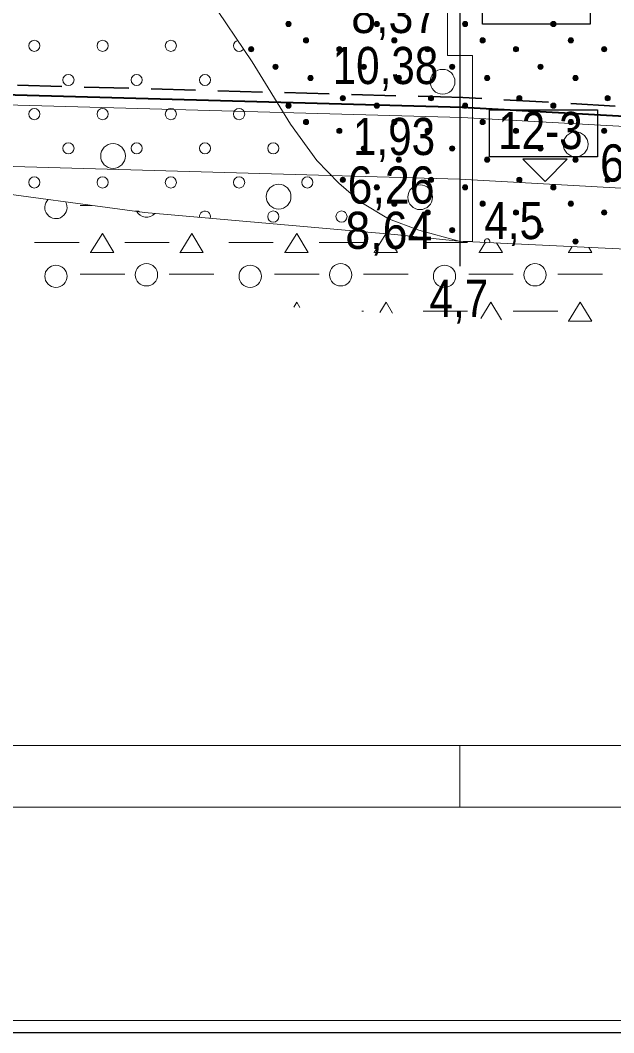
# Model space of a CAD drawing. Extents: x 640104 to 640970, y 6442278 to 6442689.
# Drawn here: x 640378.9 to 640426.8, y 6442282.5 to 6442364.3 of the extents above; entities that cross this region are included whole.
import ezdxf
from ezdxf.enums import TextEntityAlignment as Align

# ---------------------------------------------------------------- set-up
doc = ezdxf.new("R2010")
doc.units = 0
doc.header["$LTSCALE"] = 1.2
doc.linetypes.add('MEDIUM_DASHED', pattern=[4.5, 3, -1.5])
for name, color, linetype, lineweight in [('30', 7, 'Continuous', 13), ('31', 7, 'Continuous', 13), ('32', 7, 'Continuous', 25), ('33', 7, 'Continuous', 13), ('34', 7, 'Continuous', 25), ('35', 7, 'Continuous', 35), ('42', 7, 'Continuous', 13), ('44', 7, 'Continuous', 13), ('46', 7, 'Continuous', 13), ('47', 7, 'Continuous', 13), ('50', 7, 'Continuous', 13)]:
    doc.layers.add(name, color=color, linetype=linetype, lineweight=lineweight)

msp = doc.modelspace()

# ---------------------------------------------------------------- hatches: boundary and pattern name
at = {"layer": '44'}
for points in [[(640400.776, 6442364.001, 1), (640400.356, 6442364.001, 1)], [(640407.909, 6442364.001, 1), (640407.489, 6442364.001, 1)], [(640415.042, 6442364.001, 1), (640414.622, 6442364.001, 1)], [(640422.175, 6442364.001, 1), (640421.755, 6442364.001, 1)], [(640402.195, 6442362.679, 1), (640401.775, 6442362.679, 1)], [(640409.328, 6442362.679, 1), (640408.908, 6442362.679, 1)], [(640416.461, 6442362.679, 1), (640416.041, 6442362.679, 1)], [(640423.594, 6442362.679, 1), (640423.174, 6442362.679, 1)], [(640397.754, 6442361.963, 1), (640397.334, 6442361.963, 1)], [(640404.887, 6442361.963, 1), (640404.467, 6442361.963, 1)], [(640412.02, 6442361.963, 1), (640411.6, 6442361.963, 1)], [(640419.153, 6442361.963, 1), (640418.733, 6442361.963, 1)], [(640426.286, 6442361.963, 1), (640425.866, 6442361.963, 1)], [(640399.732, 6442360.544, 1), (640399.312, 6442360.544, 1)], [(640406.865, 6442360.544, 1), (640406.445, 6442360.544, 1)], [(640413.998, 6442360.544, 1), (640413.578, 6442360.544, 1)], [(640421.131, 6442360.544, 1), (640420.711, 6442360.544, 1)], [(640402.559, 6442359.636, 1), (640402.139, 6442359.636, 1)], [(640409.692, 6442359.636, 1), (640409.272, 6442359.636, 1)], [(640416.825, 6442359.636, 1), (640416.405, 6442359.636, 1)], [(640423.958, 6442359.636, 1), (640423.538, 6442359.636, 1)], [(640405.161, 6442358.01, 1), (640404.741, 6442358.01, 1)], [(640412.294, 6442358.01, 1), (640411.874, 6442358.01, 1)], [(640419.427, 6442358.01, 1), (640419.007, 6442358.01, 1)], [(640426.56, 6442358.01, 1), (640426.14, 6442358.01, 1)], [(640400.776, 6442357.405, 1), (640400.356, 6442357.405, 1)], [(640407.909, 6442357.405, 1), (640407.489, 6442357.405, 1)], [(640415.042, 6442357.405, 1), (640414.622, 6442357.405, 1)], [(640422.175, 6442357.405, 1), (640421.755, 6442357.405, 1)], [(640402.195, 6442356.083, 1), (640401.775, 6442356.083, 1)], [(640404.887, 6442355.367, 1), (640404.467, 6442355.367, 1)], [(640409.328, 6442356.083, 1), (640408.908, 6442356.083, 1)], [(640412.02, 6442355.367, 1), (640411.6, 6442355.367, 1)], [(640416.461, 6442356.083, 1), (640416.041, 6442356.083, 1)], [(640419.153, 6442355.367, 1), (640418.733, 6442355.367, 1)], [(640423.594, 6442356.083, 1), (640423.174, 6442356.083, 1)], [(640426.286, 6442355.367, 1), (640425.866, 6442355.367, 1)], [(640406.865, 6442353.948, 1), (640406.445, 6442353.948, 1)], [(640413.998, 6442353.948, 1), (640413.578, 6442353.948, 1)], [(640421.131, 6442353.948, 1), (640420.711, 6442353.948, 1)], [(640409.692, 6442353.04, 1), (640409.272, 6442353.04, 1)], [(640416.825, 6442353.04, 1), (640416.405, 6442353.04, 1)], [(640423.958, 6442353.04, 1), (640423.538, 6442353.04, 1)], [(640405.161, 6442351.414, 1), (640404.741, 6442351.414, 1)], [(640412.294, 6442351.414, 1), (640411.874, 6442351.414, 1)], [(640419.427, 6442351.414, 1), (640419.007, 6442351.414, 1)], [(640426.56, 6442351.414, 1), (640426.14, 6442351.414, 1)], [(640407.909, 6442350.809, 1), (640407.489, 6442350.809, 1)], [(640415.042, 6442350.809, 1), (640414.622, 6442350.809, 1)], [(640422.175, 6442350.809, 1), (640421.755, 6442350.809, 1)], [(640409.328, 6442349.487, 1), (640408.908, 6442349.487, 1)], [(640412.02, 6442348.771, 1), (640411.6, 6442348.771, 1)], [(640416.461, 6442349.487, 1), (640416.041, 6442349.487, 1)], [(640419.153, 6442348.771, 1), (640418.733, 6442348.771, 1)], [(640423.594, 6442349.487, 1), (640423.174, 6442349.487, 1)], [(640426.286, 6442348.771, 1), (640425.866, 6442348.771, 1)], [(640413.998, 6442347.352, 1), (640413.578, 6442347.352, 1)], [(640421.131, 6442347.352, 1), (640420.711, 6442347.352, 1)], [(640423.958, 6442346.444, 1), (640423.538, 6442346.444, 1)]]:
    msp.add_hatch(color=256, dxfattribs=at).paths.add_polyline_path(points)

# ---------------------------------------------------------------- linework, layer by layer
at = {"layer": '30'}
for p, q in [((640112.44, 6442305.75), (640578.08, 6442305.75)), ((640414.42, 6442300.75), (640414.42, 6442305.75)), ((640112.44, 6442300.75), (640578.08, 6442300.75))]:
    msp.add_line(p, q, dxfattribs=at)
at = {"layer": '31'}
for points in [[(640139.08, 6442391.74), (640152, 6442391.74), (640184.83, 6442387.53), (640224.44, 6442383.27), (640230.93, 6442382.67), (640242.81, 6442381.6), (640246.59, 6442379.93), (640268.17, 6442370.27), (640295.32, 6442359.75), (640299.34, 6442358.9), (640322.09, 6442356.12), (640340.84, 6442354.22), (640374.54, 6442350.71), (640388.93, 6442348.78), (640409.14, 6442347), (640414.32, 6442346.47), (640439.11, 6442345.27), (640478.03, 6442341.77)], [(640378.94, 6442380.49), (640381.24, 6442378.61), (640384.95, 6442375.32), (640388.74, 6442372.1), (640391.96, 6442369.01), (640394.21, 6442366.04), (640397.64, 6442360.95), (640400.72, 6442355.9), (640402.85, 6442352.99), (640404.64, 6442351.14), (640406.4, 6442349.6), (640408.64, 6442348.27), (640411.09, 6442347.36), (640414.25, 6442346.48)]]:
    msp.add_lwpolyline(points, dxfattribs=at)
at = {"layer": '32'}
msp.add_line((640414.42, 6442391.45), (640414.42, 6442344.45), dxfattribs=at)
at = {"layer": '33'}
for points in [[(640413.42, 6442371.45), (640413.42, 6442361.45), (640414.42, 6442361.45), (640414.42, 6442371.42), (640414.41, 6442371.42), (640413.58, 6442371.45)], [(640415.42, 6442346.45), (640415.42, 6442361.45), (640414.42, 6442361.45), (640414.42, 6442346.47), (640414.42, 6442346.47), (640414.68, 6442346.45)]]:
    msp.add_lwpolyline(points, close=True, dxfattribs=at)
at = {"layer": '33', "lineweight": 25}
for points in [[(640416.24, 6442367.78), (640424.95, 6442367.78), (640424.95, 6442363.98), (640416.24, 6442363.98)], [(640416.81, 6442357.07), (640425.52, 6442357.07), (640425.52, 6442353.27), (640416.81, 6442353.27)]]:
    msp.add_lwpolyline(points, close=True, dxfattribs=at)
at = {"layer": '34', "lineweight": 13}
msp.add_lwpolyline([(640577.98, 6442339.23), (640519.43, 6442345.64), (640414.37, 6442351.46), (640348.88, 6442353.33)], dxfattribs=at)
at = {"layer": '34'}
msp.add_lwpolyline([(640419.51, 6442353.09), (640421.3, 6442351.27), (640423.08, 6442353.08)], close=True, dxfattribs=at)
at = {"layer": '35', "linetype": 'MEDIUM_DASHED'}
msp.add_lwpolyline([(640518.62, 6442352.3), (640414.65, 6442358.06), (640295.64, 6442361.35)], dxfattribs=at)
at = {"layer": '35', "lineweight": 40}
msp.add_lwpolyline([(640518.52, 6442351.5), (640414.61, 6442357.26), (640295.48, 6442360.55)], dxfattribs=at)
at = {"layer": '35', "lineweight": 13}
msp.add_lwpolyline([(640519.42, 6442350.65), (640414.58, 6442356.46), (640295.32, 6442359.75)], dxfattribs=at)
at = {"layer": '42'}
for centre in [(640380.031, 6442362.238), (640385.547, 6442362.238), (640391.062, 6442362.238), (640382.789, 6442359.481), (640388.304, 6442359.481), (640393.82, 6442359.481), (640380.031, 6442356.723), (640385.547, 6442356.723), (640391.062, 6442356.723), (640396.578, 6442356.723), (640382.789, 6442353.965), (640388.304, 6442353.965), (640393.82, 6442353.965), (640399.335, 6442353.965), (640380.031, 6442351.207), (640385.547, 6442351.207), (640391.062, 6442351.207), (640396.578, 6442351.207), (640402.093, 6442351.207), (640399.335, 6442348.45), (640404.851, 6442348.45)]:
    msp.add_circle(centre, 0.45, dxfattribs=at)
for centre, start, end in [((640396.578, 6442362.238), 103.0976, 324.82819), ((640388.304, 6442348.45), 58.9198, 105.79939), ((640393.82, 6442348.45), 342.42211, 187.51262)]:
    msp.add_arc(centre, 0.45, start, end, dxfattribs=at)
at = {"layer": '44'}
for centre in [(640400.566, 6442364.001), (640407.699, 6442364.001), (640414.832, 6442364.001), (640421.965, 6442364.001), (640401.985, 6442362.679), (640409.118, 6442362.679), (640416.251, 6442362.679), (640423.384, 6442362.679), (640397.544, 6442361.963), (640404.677, 6442361.963), (640411.81, 6442361.963), (640418.943, 6442361.963), (640426.076, 6442361.963), (640399.522, 6442360.544), (640406.655, 6442360.544), (640413.788, 6442360.544), (640420.921, 6442360.544), (640402.349, 6442359.636), (640409.482, 6442359.636), (640416.615, 6442359.636), (640423.748, 6442359.636), (640404.951, 6442358.01), (640412.084, 6442358.01), (640419.217, 6442358.01), (640426.35, 6442358.01), (640400.566, 6442357.405), (640407.699, 6442357.405), (640414.832, 6442357.405), (640421.965, 6442357.405), (640401.985, 6442356.083), (640404.677, 6442355.367), (640409.118, 6442356.083), (640411.81, 6442355.367), (640416.251, 6442356.083), (640418.943, 6442355.367), (640423.384, 6442356.083), (640426.076, 6442355.367), (640406.655, 6442353.948), (640413.788, 6442353.948), (640420.921, 6442353.948), (640409.482, 6442353.04), (640416.615, 6442353.04), (640423.748, 6442353.04), (640404.951, 6442351.414), (640412.084, 6442351.414), (640419.217, 6442351.414), (640426.35, 6442351.414), (640407.699, 6442350.809), (640414.832, 6442350.809), (640421.965, 6442350.809), (640409.118, 6442349.487), (640411.81, 6442348.771), (640416.251, 6442349.487), (640418.943, 6442348.771), (640423.384, 6442349.487), (640426.076, 6442348.771), (640413.788, 6442347.352), (640420.921, 6442347.352), (640423.748, 6442346.444)]:
    msp.add_circle(centre, 0.21, dxfattribs=at)
msp.add_arc((640416.615, 6442346.444), 0.21, 333.58593, 200.85041, dxfattribs=at)
at = {"layer": '46'}
for p, q in [((640384.67, 6442349.35), (640383.74, 6442349.35)), ((640383.65, 6442346.36), (640380.05, 6442346.36)), ((640390.94, 6442346.35), (640387.34, 6442346.35)), ((640399.34, 6442346.36), (640395.74, 6442346.36)), ((640406.64, 6442346.35), (640403.04, 6442346.35)), ((640415.04, 6442346.36), (640411.44, 6442346.36)), ((640387.34, 6442343.8), (640383.74, 6442343.8)), ((640394.54, 6442343.79), (640390.94, 6442343.79)), ((640403.04, 6442343.8), (640399.44, 6442343.8)), ((640410.24, 6442343.79), (640406.64, 6442343.79)), ((640418.73, 6442343.8), (640415.13, 6442343.8)), ((640425.93, 6442343.79), (640422.33, 6442343.79)), ((640406.64, 6442340.8), (640406.5, 6442340.8)), ((640415.04, 6442340.8), (640411.44, 6442340.8)), ((640422.33, 6442340.8), (640418.73, 6442340.8))]:
    msp.add_line(p, q, dxfattribs=at)
for points in [[(640384.58, 6442345.53), (640384.58, 6442345.55), (640385.53, 6442347.08), (640386.46, 6442345.54), (640384.66, 6442345.55)], [(640391.8, 6442345.53), (640391.81, 6442345.55), (640392.75, 6442347.08), (640393.68, 6442345.54), (640391.88, 6442345.55)], [(640400.28, 6442345.53), (640400.28, 6442345.55), (640401.23, 6442347.08), (640402.16, 6442345.54), (640400.36, 6442345.55)], [(640407.5, 6442345.53), (640407.5, 6442345.55), (640408.44, 6442347.06)], [(640408.46, 6442347.06), (640409.38, 6442345.54), (640407.58, 6442345.55)], [(640415.97, 6442345.53), (640415.98, 6442345.55), (640416.48, 6442346.37)], [(640417.38, 6442346.32), (640417.85, 6442345.54), (640416.05, 6442345.55)], [(640423.19, 6442345.53), (640423.2, 6442345.55), (640423.49, 6442346.03)], [(640424.82, 6442345.96), (640425.07, 6442345.54), (640423.27, 6442345.55)], [(640400.99, 6442341.14), (640401.23, 6442341.53), (640401.48, 6442341.11)], [(640407.94, 6442340.71), (640408.45, 6442341.53), (640408.98, 6442340.65)], [(640416.11, 6442340.21), (640416.92, 6442341.53), (640417.78, 6442340.11)], [(640423.19, 6442339.97), (640423.2, 6442340), (640424.14, 6442341.53), (640425.07, 6442339.99), (640423.27, 6442340)]]:
    msp.add_lwpolyline(points, dxfattribs=at)
for centre in [(640381.778, 6442343.626), (640389.091, 6442343.748), (640397.473, 6442343.626), (640404.786, 6442343.748), (640413.169, 6442343.626), (640420.482, 6442343.748)]:
    msp.add_circle(centre, 0.9, dxfattribs=at)
for centre, start, end in [((640381.778, 6442349.181), 134.19567, 30.52352), ((640389.091, 6442349.303), 209.01187, 318.67315)]:
    msp.add_arc(centre, 0.9, start, end, dxfattribs=at)
at = {"layer": '47'}
for centre in [(640413.016, 6442359.338), (640423.765, 6442354.287), (640386.394, 6442353.344), (640399.769, 6442350.061), (640411.203, 6442350.013)]:
    msp.add_circle(centre, 1, dxfattribs=at)
at = {"layer": '50', "lineweight": 25}
msp.add_lwpolyline([(640103.56, 6442688.99), (640970.3, 6442688.99), (640970.3, 6442282.54), (640103.56, 6442282.54)], close=True, dxfattribs=at)
at = {"layer": '50'}
msp.add_lwpolyline([(640104.56, 6442687.99), (640969.3, 6442687.99), (640969.3, 6442283.54), (640104.56, 6442283.54)], close=True, dxfattribs=at)

# ---------------------------------------------------------------- texts
at = {"layer": '32', "width": 0.85}
for s, p in [('4,5', (640418.765, 6442346.63)), ('4,7', (640414.33, 6442340.35))]:
    msp.add_text(s, height=3, dxfattribs=at).set_placement(p, align=Align.CENTER)
at = {"layer": '33'}
for s, width, p in [('8,37', 0.9, (640409.15, 6442363.27)), ('10,38', 0.85, (640408.4, 6442359.15)), ('1,93', 0.85, (640409.095, 6442353.42)), ('12-3', 0.85, (640420.92, 6442353.9)), ('6,26', 0.9, (640408.855, 6442349.5)), ('8,64', 0.9, (640408.675, 6442345.84))]:
    msp.add_text(s, height=3, dxfattribs=dict(at, width=width)).set_placement(p, align=Align.CENTER)
at = {"layer": '34', "width": 0.9}
msp.add_text('63,07', height=3, dxfattribs=at).set_placement((640430.25, 6442351.28), align=Align.CENTER)

doc.saveas('drawing.dxf')
